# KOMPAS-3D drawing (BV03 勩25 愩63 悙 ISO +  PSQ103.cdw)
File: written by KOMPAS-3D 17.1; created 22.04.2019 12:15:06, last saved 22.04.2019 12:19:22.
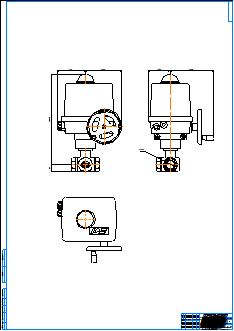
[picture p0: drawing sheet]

Sheet 1: A0, portrait

Title block, sheet 1: name: BV03 Ду25 Ру63 РР ISO + / PSQ103; material: Внимание! Данный продукт является объектом авторского права ООО «Торговый Дом АДЛ». / Запрещается изменение, копирование, распространение / (в том числе путем копирования на другие сайты и ресурсы в Интернете) / или любое иное использование информации и объектов без предварительного / согласия правообладателя (ООО «Торговый Дом АДЛ»).; mass: 40,8; sheets: 1; organisation: ООО "Торговый дом АДЛ"; sheet format: A0

Views: Спереди 1, Проекционный вид 2, Проекционный вид 3
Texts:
  user
Dimensions and other numbers on the sheet: 103; 130,2; 326,7; 26; 78,95; 156,34; 33,25; 1:1; 1; 40,8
